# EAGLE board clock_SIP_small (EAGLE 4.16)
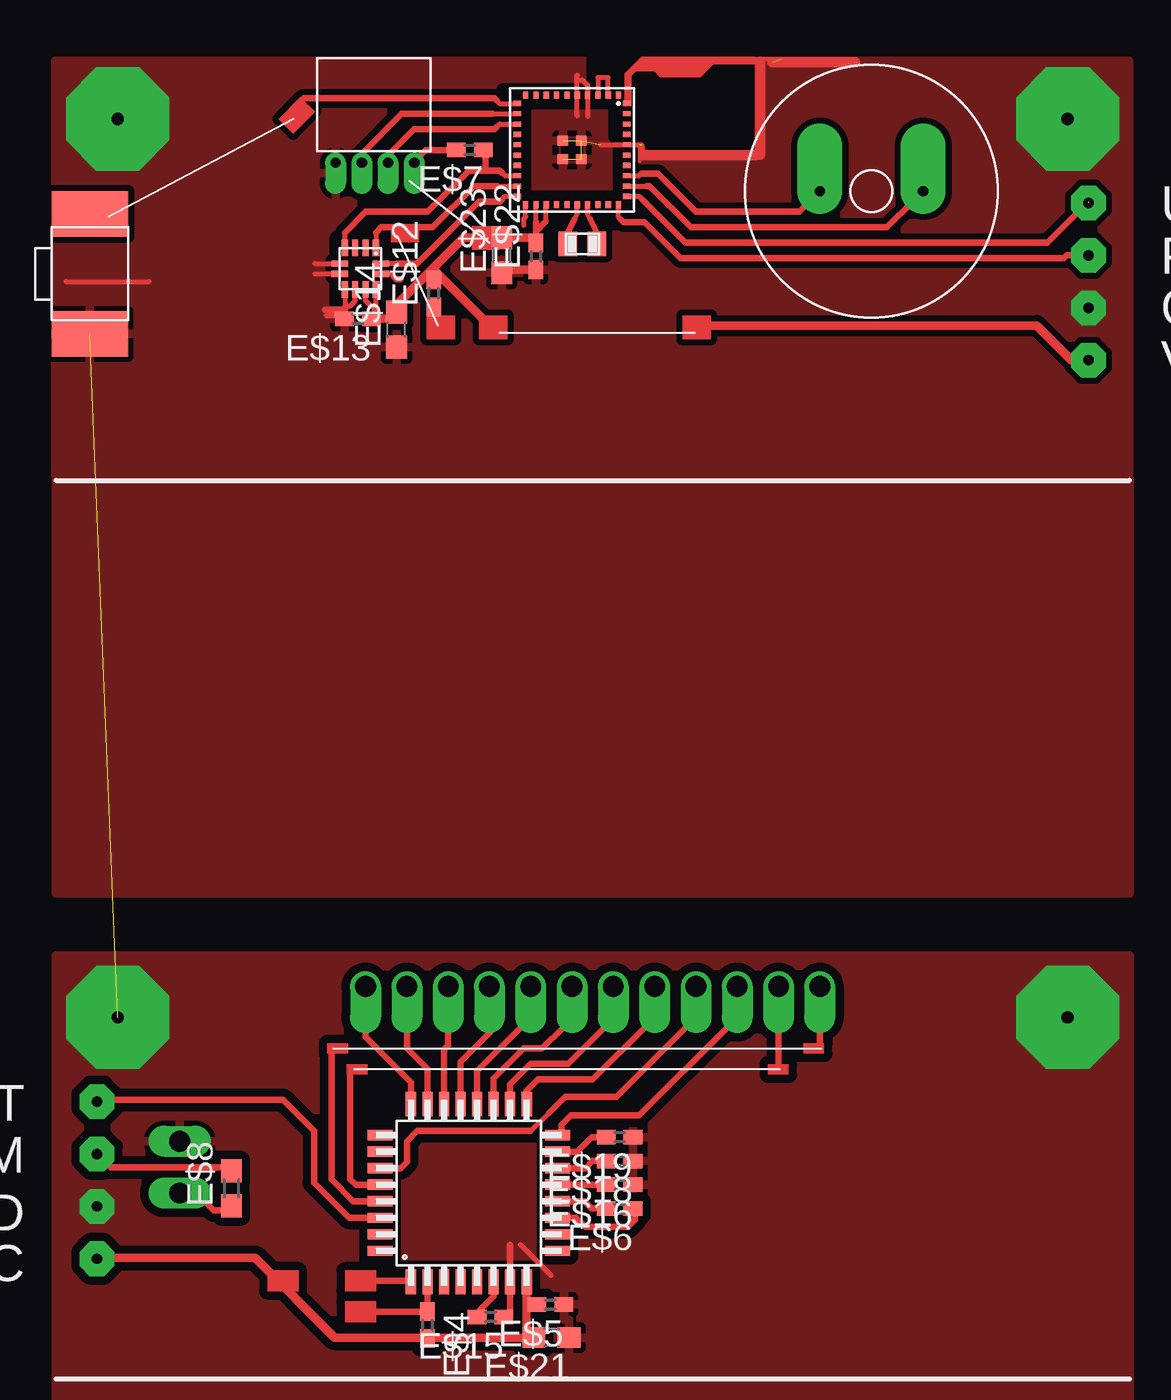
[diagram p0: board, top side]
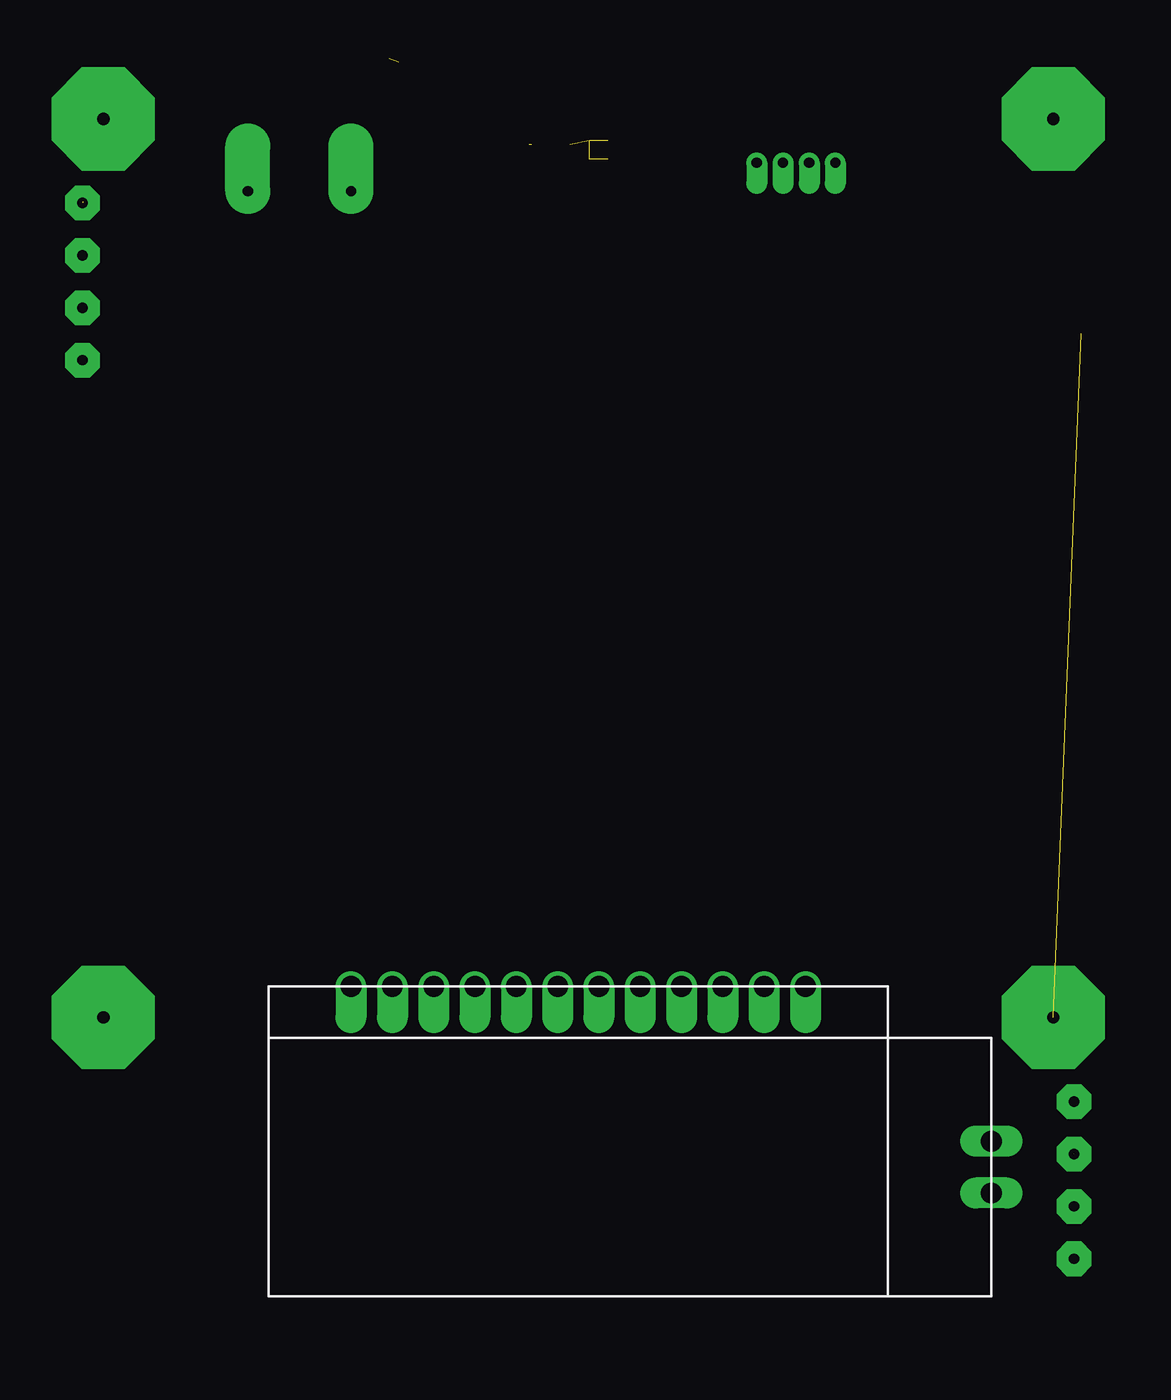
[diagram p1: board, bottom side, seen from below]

No outline drawn. Coordinates in mm, seen from the top.
Copper layers (1*16): Top 0.035mm / dielectric 1.5mm / Bottom 0.035mm
Design rules "default": minimum track width 10mil, minimum drill 24mil, track to track 8mil, track to pad 8mil, pad to pad 8mil, via to via 8mil, smd to smd 8mil, copper to edge 40mil, drill to drill 8mil, minimum pad ring 10mil, minimum via ring 8mil, stop-mask expansion 4mil, vias tented up to drill 0mil, thermal gap 10mil
tRestrict: area 27.1,80.2 to 33.6,83; area 26,83 to 27.5,84; area 28.8,79.8 to 33.6,81; area 24.8,79.3 to 25.2,79.8; 8 lines

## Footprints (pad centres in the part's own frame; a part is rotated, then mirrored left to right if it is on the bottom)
LGA12 = smd 0.8 x 0.3: 1 -0.75,0.5; 2 -0.75,0; 3 -0.75,-0.5; 4 -0.75,-1; 7 1.25,-1; 8 1.25,-0.5; 9 1.25,0; 10 1.25,0.5 | smd 0.3 x 0.8: 5 0,-1.25; 6 0.5,-1.25; 11 0.5,0.75; 12 0,0.75
ALI_4D_S = drill 1 offset: 1 4,0; 2 6,0; 3 8,0; 4 10,0; 5 12,0; 6 14,0; 7 16,0; 8 18,0; 9 20,0; 10 22,0; 11 24,0; 12 26,0 | drill 1 long: A -5,7.5; K -5,10
LQFP32 = smd 1.2 x 0.5: 1 -4.3,2.8; 2 -4.3,2; 3 -4.3,1.2; 4 -4.3,0.4; 5 -4.3,-0.4; 6 -4.3,-1.2; 7 -4.3,-2; 8 -4.3,-2.8; 17 4.3,-2.8; 18 4.3,-2; 19 4.3,-1.2; 20 4.3,-0.4; 21 4.3,0.4; 22 4.3,1.2; 23 4.3,2; 24 4.3,2.8 | smd 0.5 x 1.2: 9 -2.8,-4.3; 10 -2,-4.3; 11 -1.2,-4.3; 12 -0.4,-4.3; 13 0.4,-4.3; 14 1.2,-4.3; 15 2,-4.3; 16 2.8,-4.3; 25 2.8,4.3; 26 2,4.3; 27 1.2,4.3; 28 0.4,4.3; 29 -0.4,4.3; 30 -1.2,4.3; 31 -2,4.3; 32 -2.8,4.3
C0402 = smd 0.9 x 0.7: 1 -0.65,0; 2 0.65,0
R0603 = smd 1.1 x 1: 1 -0.85,0; 2 0.85,0
BUZZ_12MM = drill 0.5 pad 2.184 offset: P$1 -2.5,0; P$2 2.5,0
HEADER4S_R = drill 0.5 offset: P$1 0,-1.27; P$2 1.27,-1.27; P$3 2.54,-1.27; P$4 3.81,-1.27
KSS = smd 2.2 x 3.7: P$1 -2.9,0; P$2 2.9,0
C0603 = smd 1.1 x 1: 1 -0.85,0; 2 0.85,0
BGM220SIP = smd 0.35 x 0.25: 1 -2.65,2.25; 2 -2.65,1.75; 3 -2.65,1.25; 4 -2.65,0.75; 5 -2.65,0.25; 6 -2.65,-0.25; 7 -2.65,-0.75; 8 -2.65,-1.25; 9 -2.65,-1.75; 10 -2.65,-2.25; 21 2.65,-2.25; 22 2.65,-1.75; 23 2.65,-1.25; 24 2.65,-0.75; 25 2.65,-0.25; 26 2.65,0.25; 27 2.65,0.75; 28 2.65,1.25; 29 2.65,1.75; 30 2.65,2.25 | smd 0.25 x 0.35: 11 -2.25,-2.65; 12 -1.75,-2.65; 13 -1.25,-2.65; 14 -0.75,-2.65; 15 -0.25,-2.65; 16 0.25,-2.65; 17 0.75,-2.65; 18 1.25,-2.65; 19 1.75,-2.65; 20 2.25,-2.65; 31 2.25,2.65; 32 1.75,2.65; 33 1.25,2.65; 34 0.75,2.65; 35 0.25,2.65; 36 -0.25,2.65; 37 -0.75,2.65; 38 -1.25,2.65; 39 -1.75,2.65; 40 -2.25,2.65 | smd 0.5 x 0.5: 41 -0.45,0.45; 42 -0.45,-0.45; 43 0.45,-0.45; 44 0.45,0.45
ECS_2216 = smd 0.9 x 1.2: P$1 -0.7,0; P$2 0.7,0

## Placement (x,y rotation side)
E$1  [LGA12]  15,74 270 top
E$2  [ALI_4D_S]  11,39 180 bottom
E$3  [LQFP32]  20,29 90 top
E$4  [C0402]  18,22.6 270 top
E$5  [C0402]  23.95,23.6 180 top
E$6  [C0402]  27.3,28.25 180 top
E$7  [C0402]  20.05,79.5 180 top
E$8  [R0603]  8.5,29.23 90 top
E$9  [BUZZ_12MM]  39.5,77.5 0 top
E$10  [HEADER4S_R]  13.55,80.15 0 top
E$11  [KSS]  1.65,73.5 270 top
E$12  [C0402]  18.3,72.55 90 top
E$13  [C0402]  14.62,71.33 180 top
E$14  [C0603]  16.5,70.8 90 top
E$15  [C0402]  21.05,23 180 top
E$16  [C0402]  27.3,29.4 180 top
E$17  [BGM220SIP]  25,79.5 270 top
E$18  [C0402]  27.3,30.55 180 top
E$19  [C0402]  27.3,31.7 180 top
E$20  [ECS_2216]  25.5,74.95 0 top
E$21  [C0603]  24,22 180 top
E$22  [C0402]  23.25,74.35 90 top
E$23  [C0603]  21.6,74.4 90 top

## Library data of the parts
E$1 = st-microelectronics
E$2 = display-lcd
E$3 = renesas
E$4-E$7 E$12-E$16 E$18 E$19 E$21-E$23 = ref-packages
E$8 = rcl
E$9 = buzzer
E$10 = sb
E$11 = switch-misc
E$17 = silabs
E$20 = crystal

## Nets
GND1: E$2.A E$5.1 E$10.P$1 E$11.P$2 E$13.2 E$14.1 E$16.1 E$17.41 E$17.42 E$17.43 E$17.44 E$18.1 E$19.1 E$21.1 E$22.1 E$23.1
S$53: E$2.K

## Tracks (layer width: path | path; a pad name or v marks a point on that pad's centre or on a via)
GND1  (via drill 0.5 pad 1.68, 0.6 pad 5)  (7 unrouted)
  Top 0.2: 32.66,83.91 35.16,83.91 | 28.27,79.75 28.27,78.97
  Top 0.25: 28.38,79.37 28.38,79.75 26.4,79.75 | 25.25,82.88 25.25,83.14 | 25.25,81.14 25.25,82.88 | 25.25,82.88 25.5,82.88 25.75,82.64 25.75,81.12 | 24,25 22.5,26.5
  Top 0.254: 14.5,72.5 14.5,72.19 14.25,71.94 14,71.94 | 14,71.94 14,71.78 | 14,72.5 14,71.94 | 12.55,73.5 13.5,73.5 | 12.55,74 13.5,74 | 0.5,73.12 4.5,73.12
  Top 0.305: 13.05,71.78 14,71.78 14,71.5 13.14,71.5 | 22,23 22,26.5
  Top 0.406: 22,73.7 23,73.7
  Top 0.5: 29.39,79.25 32.89,79.25 | 29.39,79.25 28.49,79.25 | 29.39,79.25 33.89,79.25 | 34.1,79.26 34.1,83.76 | 34.69,83.75 38.69,83.75
  other vias: 3,81 49,81 49,37.5 3,37.5 2,28.35 50,71.86
  pour Top (isolate 0.406): 0,0 0,40.5 52,40.5 52,0
  pour Top (isolate 0.305): 0,43.5 -0.02,83.82 51.97,83.81 52,43.5
S$1
  Top 0.305: 15,37 15,36.55 17.2,34.35 17.2,33.8
S$2
  Top 0.254: 14,75 14,75.47
S$3
  Top 0.305: 21,37 21,36.75 19.6,35.35 19.6,33.6
S$4
  Top 0.305: 17,37 17,36 18,35 18,33.5
S$5
  Top 0.305: 19,37 19,36.15 18.8,35.95 18.8,33.5
S$6
  Top 0.25: 22.35,81.75 21.5,81.75 21.35,81.9
  Top 0.305: 11,81 12,82 21.25,82 21.35,81.9
S$7
  Top 0.25: 21.6,78.4 21.75,78.25 22.4,78.25
  Top 0.305: 14,75.5 15,76.5 18,76.5 20,78.5 20.8,78.5 | 20.8,78.5 21.5,78.5 21.6,78.4 | 20.8,78.5 20.8,79.5
S$8
  Top 0.25: 15.5,75.5 15.5,75 | 21.4,77.75 22.4,77.75
  Top 0.305: 15.5,75.5 15.75,75.75 18.25,75.75 20.25,77.75 21.4,77.75
S$9
  Top 0.406: 21.1,70.9 18.3,73.7
S$10
  Top 0.25: 21.6,77.1 21.75,77.25 22.35,77.25
  Top 0.305: 16.5,74 17.5,74 20.5,77 21.5,77 21.6,77.1
S$11
  Top 0.25: 23,32 23.9,32.9
  Top 0.305: 15.95,30.2 16.7,30.2 17,30.5 17,31.5 17.5,32 23,32 | 23.9,32.9 24.65,33.65 27.15,33.65 30.5,37
S$12
  Top 0.305: 19,79.5 17.9,79.5 17.4,79
S$13
  Top 0.25: 27.65,78.25 28.25,78.25 28.35,78.35
  Top 0.305: 28.35,78.35 29.15,78.35 31,76.5 36,76.5 36.5,77
S$14
  Top 0.25: 27.75,77.75 28.6,77.75
  Top 0.305: 28.6,77.75 28.75,77.75 30.75,75.75 40.25,75.75 41.5,77
S$15
  Top 0.25: 27.25,76.75 27.25,76.25 27.4,76.1
  Top 0.305: 27.4,76.1 27.5,76 28.5,76 30.25,74.25 48.8,74.25 48.95,74.4 50.1,74.4
S$16
  Top 0.305: 37,37.05 37,36
S$17
  Top 0.305: 34.99,35.05 34.99,37.01
S$18  (via drill 0.5 pad 1.68)  (1 unrouted)
  Top 0.305: v2,30.9 2.65,30.25 8.75,30.25
S$19
  Top 0.254: 16.38,74 16,74
S$20
  Top 0.305: 20.4,33.5 20.4,34.9 22.55,37.05
S$21
  Top 0.305: 21.2,33.6 21.2,34.55 22.65,36 23.55,36 24.55,37
S$22
  Top 0.305: 22.8,33.5 22.8,33.95 23.35,34.5 26,34.5 28.5,37
S$23
  Top 0.305: 22,33.5 22,34.25 23,35.25 24.8,35.25 26.55,37
S$24
  Top 0.305: 24.5,32 24.5,32.3 24.95,32.75 28.25,32.75 32.5,37
S$25
  Top 0.406: 2,25.85 9.65,25.85 13.5,22 22.8,22 22.8,24.5
S$26
  Top 0.25: 14.25,34.85 14.25,35.05
  Top 0.305: 15.5,29.4 14.55,29.4 14.25,29.65 14.25,34.85
S$27
  Top 0.305: 15.4,28.6 14.4,28.6 13.35,29.65 13.35,35.95
S$28
  Top 0.305: 26.55,28.25 25.95,28.25 25.6,28.6 24.5,28.6
S$29
  Top 0.305: 24.5,27.8 25.2,27.8 25.65,27.35 27.7,27.35 28.05,27.7 28.05,28.15
S$30
  Top 0.25: 26.25,82.1 26.25,83 26.75,83 26.75,82.1
S$31
  Top 0.25: 25.75,76.9 25.75,76.4 25.88,76.15
  Top 0.3: 25.88,76.15 26.25,75.4
S$32  (via drill 0.5 pad 1.68)
  other vias: 50,74.4
S$33  (via drill 0.5 pad 1.68)
  other vias: 2,25.81
S$34
  Top 0.254: 15,73 15,72.2 15.26,71.94 15.5,71.94 | 15.5,71.94 15.5,72.5 | 15.5,71.94 15.5,71.8
  Top 0.406: 15.5,71.8 15.5,71.28
S$35
  Top 0.25: 26.15,29.4 26.5,29.4
  Top 0.305: 24.5,29.4 26.15,29.4
S$36
  Top 0.254: 22.65,75.85 22.65,76.15 22.75,76.25 22.75,76.75
S$37
  Top 0.305: 24.55,30.2 25.65,30.2 26,30.55 26.5,30.55
S$38
  Top 0.305: 21.2,24.5 21.2,24 20.55,23.35 20.55,23
S$39
  Top 0.305: 24.5,31 25.25,31 25.95,31.7 26.75,31.7
S$40
  Top 0.254: 16,73.5 16.23,73.5 16.4,73.33
  Top 0.305: 16.7,73.25 16.48,73.25 16.4,73.33
S$42
  Top 0.25: 25.25,76.9 25.25,76.4 25.12,76.15
  Top 0.3: 25.12,76.15 24.75,75.4
S$44
  Top 0.25: 23.75,76.85 23.75,76.05 23.7,76 | 23.25,76 23.25,76.85
  Top 0.305: 23.25,75.55 23.25,76 | 23.25,75.25 23.25,75.55 | 23.25,75.55 23.7,76
  Top 0.406: 15.6,71.33 16.5,71.33 16.5,72 19.75,75.25 23.25,75.25
S$45
  Top 0.25: 21.15,81.25 22.4,81.25
  Top 0.305: 14.85,78.95 14.85,79.35 16.75,81.25 21.15,81.25
S$46  (via drill 0.5 pad 1.68)  (1 unrouted)
  Top 0.25: 28.4,77.1 28.25,77.25 27.65,77.25
  Top 0.305: 28.4,77.1 30.5,75 48,75 50,77
  other vias: 50,76.94
S$47
  Top 0.25: 22.4,80.75 21.5,80.75 21.35,80.6
  Top 0.305: 16.1,78.9 16.1,79.25 17.35,80.5 21.25,80.5 21.35,80.6
S$48
  Top 0.305: 18,23.5 18,24.5
S$49
  Top 0.305: 15,24.75 17.05,24.75
S$50
  Top 0.305: 15,23.25 17.95,23.25
S$51  (via drill 0.5 pad 1.68)
  other vias: 2,33.43
S$52
  Top 0.305: 15.2,27.8 14.2,27.8 12.5,29.5 12.5,32 11,33.5 2,33.5
S$53
  Top 0.305: E$2.K 6.8,29 7.65,28.15 8.45,28.15
S$54
  Top 0.406: 31.5,71 47.5,71 49.2,69.3 50,69.3
S$77  (via drill 0.5 pad 1.68)
  other vias: 50,69.32
(copper drawn outside any net)
  shapes: Top area x21

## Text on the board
tPlace: UART | PWM | GND | VCC | UART | PWM | GND | VCC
